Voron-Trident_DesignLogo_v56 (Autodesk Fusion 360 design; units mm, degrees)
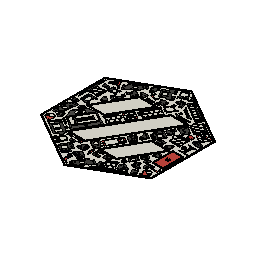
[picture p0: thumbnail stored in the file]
named bodies: "Main body", "hexagon", "filter_access_cover", "blower_housing_rear", "hotend_fan_mount", "x_carriage_frame_left", "endstop_pod_microswitch", "xy_joint_cable_bridge_xxxx", "xy_joint_left_lower", "xy_joint_right_lower", "z_belt_clip_lower_x4", "z_belt_clip_upper_x4", "z_chain_bottom_anchor", "tensioner_left", "tensioner_right", "front_idler_left_lower", "front_idler_right_lower", "front_idler_right_upper", "printhead_front_mosquito", "printhead_rear_mosquito", "skr_1.3_1.4_bracket_x2", "raspberrypi_bracket", "mini12864_spacer", "mini12864_case_front", "plug_panel", "exhaust_filter_grill", "door_hinge_x4", "door_hinge2A_x4", "door_hinge2B_x4", "handle_b_x2", "handle_b_x2_2", "handle_a_x2", "door_hinge_x4_3", "latch_x2", "bottom_panel_clip_x4", "midspan_panel_clip_6mm_x3", "corner_panel_clip_6mm_x4", "z_belt_cover_a_x2", "z_belt_cover_b_x2", "[a]_latch", "latch_shuttle", "extruder_motor_plate", "extruder_body", "[a]_cable_cover", "a_drive_frame_lower", "b_drive_frame_upper", "b_drive_frame_lower", "exhaust_filter_housing", "bowen_retainer", "spool_holder", "side_fan_support_x2", "front_rear_skirt_a_250_x2", "front_rear_skirt_b_250_x2", "side_skirt_a_250_x2", "side_skirt_b_250_x2", "[a]_60mm_fan_blank_insert_x2", "[a]_belt_tensioner_b_x2", "[a]_belt_tensioner_a_x2", "[a]_z_drive_baseplate_a_x2", "[a]_z_drive_baseplate_b_x2"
